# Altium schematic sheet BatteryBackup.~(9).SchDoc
size 431 x 279 mm; Date: Not shown in title block; ApprovedBy: Not shown in title block; CheckedBy: Not shown in title block; Author: Not shown in title block; CompanyName: Not shown in title block; Engineer: Not shown in title block; Organization: Not shown in title block; Address1: Not shown in title block; Address2: Not shown in title block; Address3: Not shown in title block; Address4: Not shown in title block; DocumentNumber: 1; Revision: Use project parameter SCH_Rev; SheetNumber: 1; SheetTotal: 2; PageSetup: Record=PageOptions¦CenterHorizontal=True¦CenterVertical=True¦PrintScale=1.00¦XCorrection=1.00¦YCorrection=1.00¦PrintKind=0¦BorderSize=5000000¦LeftOffset=0¦BottomOffset=0¦Orientation=2¦PaperLength=1000¦PaperWidth=1000¦Scale=100¦PaperSource=15¦PrintQuality=600¦MediaType=1¦DitherType=10¦PaperKind=Letter¦PrintScaleMode=1
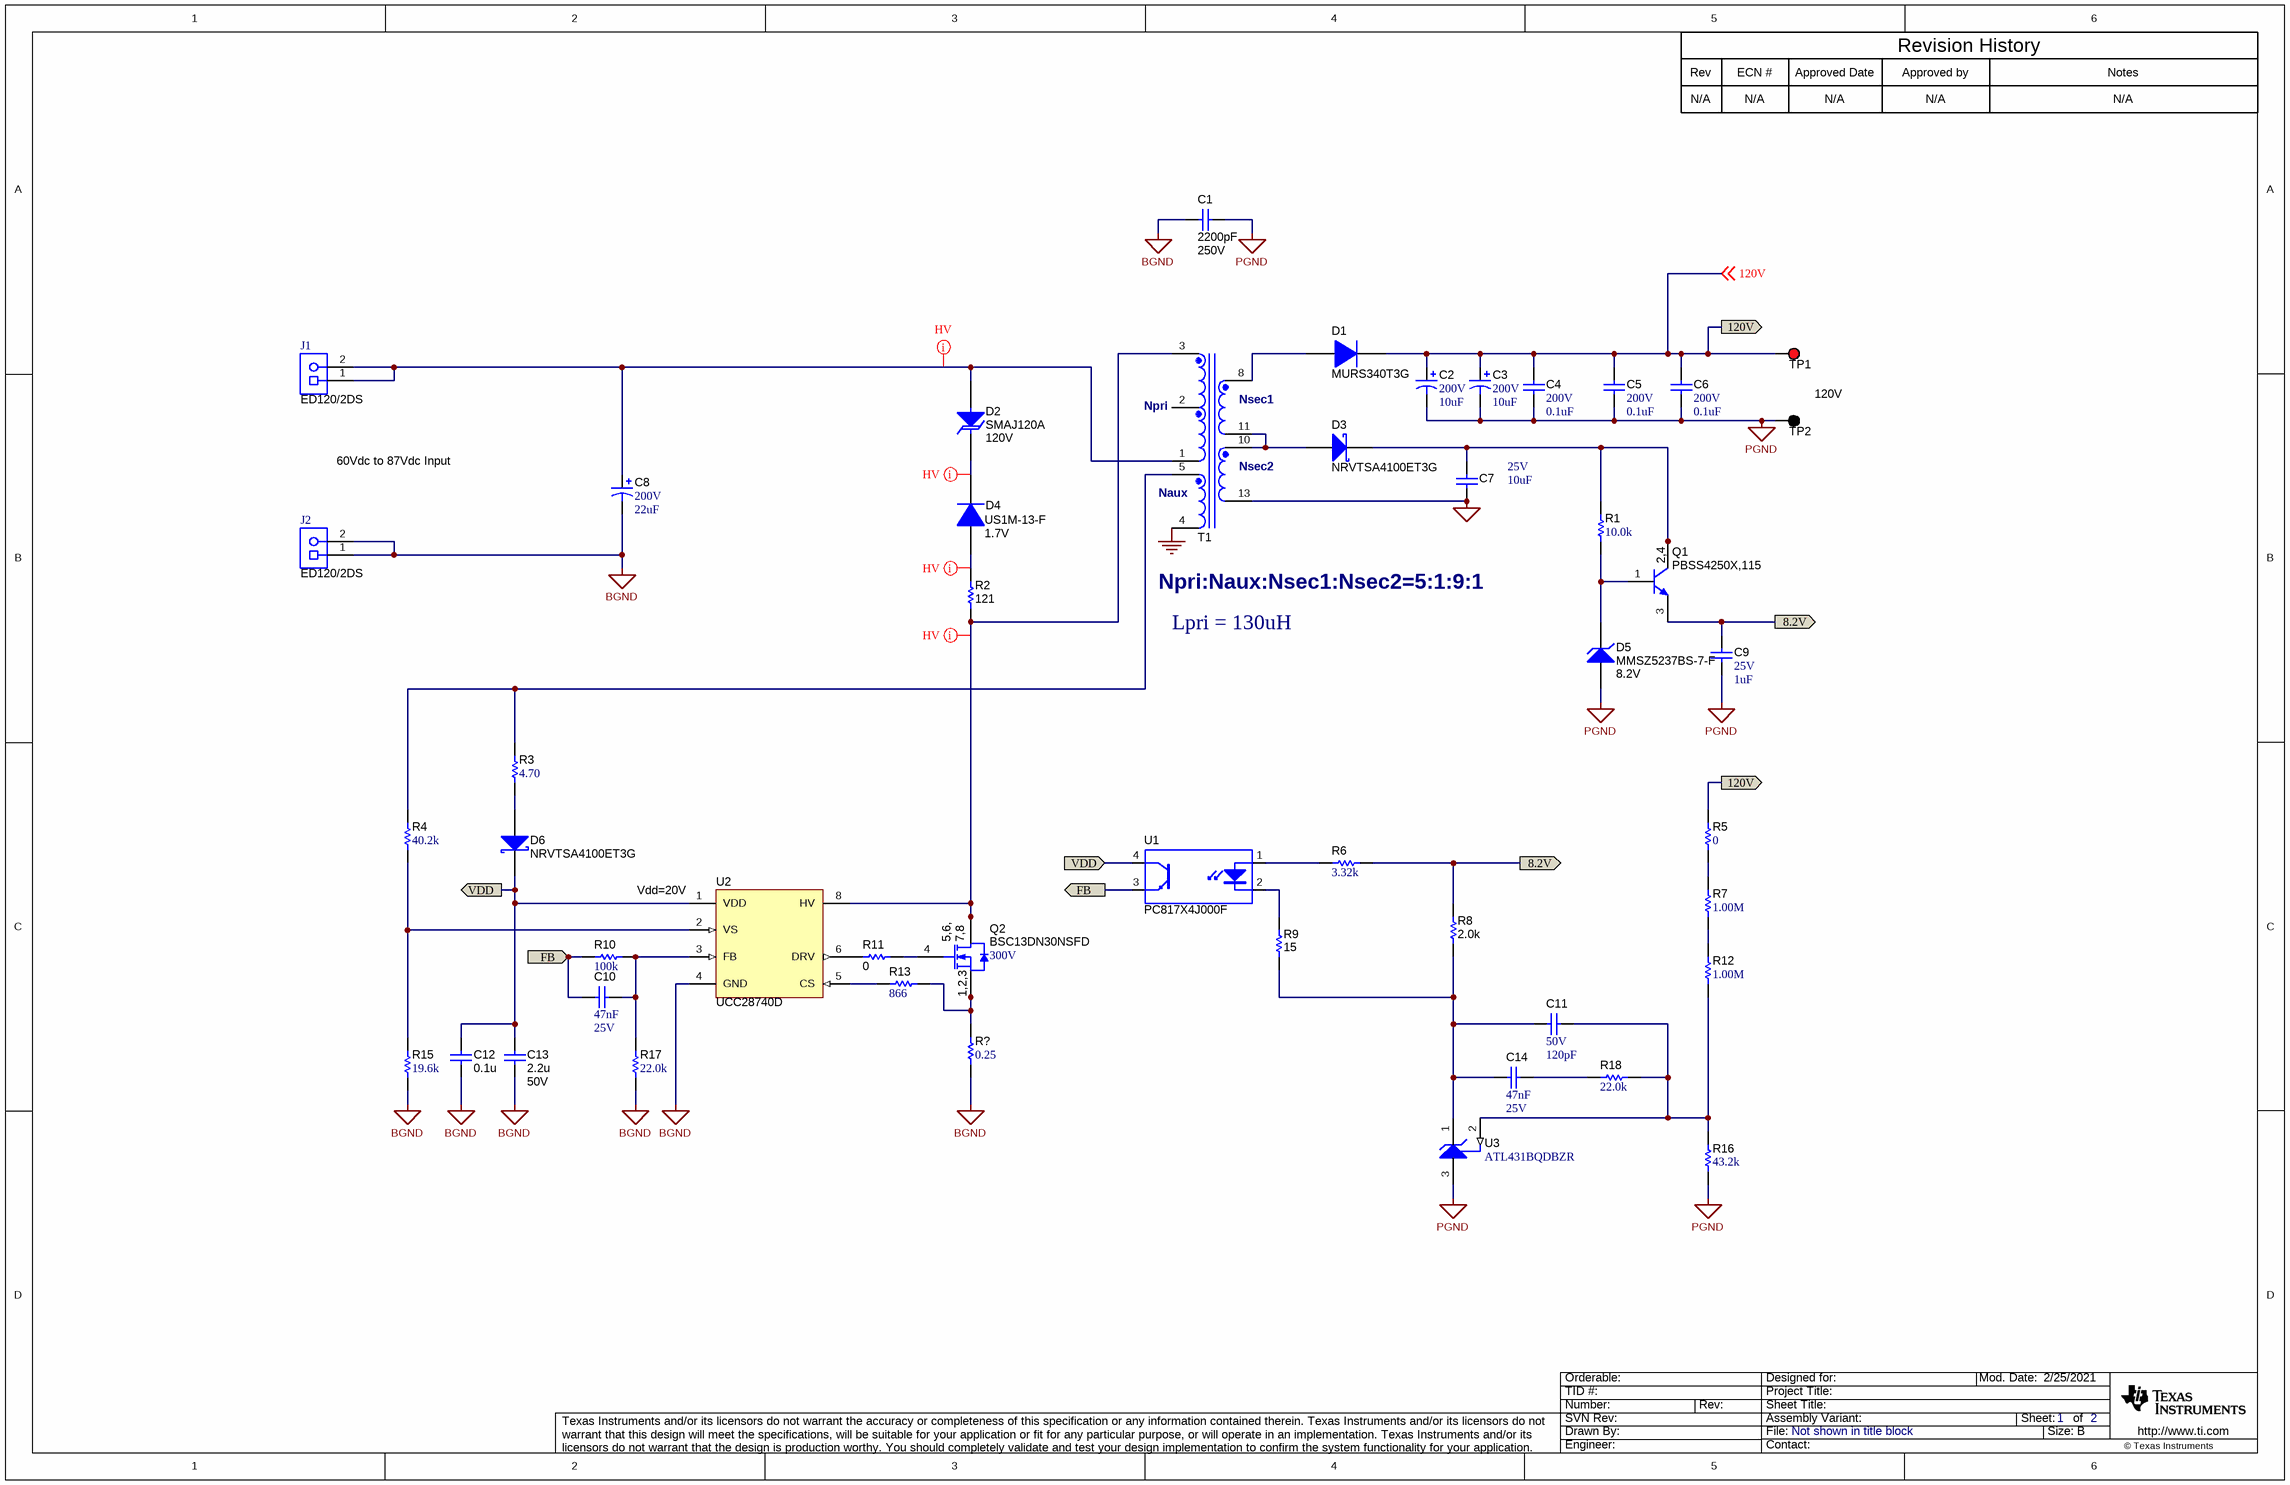
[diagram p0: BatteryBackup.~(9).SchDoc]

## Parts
C1  ValueDisplayed: 2200pF  Value2: 250V  [CAPRD750W60D1050H1450]  (hidden comment: CS11-E2GA222MYNS)
C2  VDC_V: 200V  ValueDisplayed: 10uF  [VK_800X1150]  (hidden comment: UVK2D100MPD)
C3  VDC_V: 200V  ValueDisplayed: 10uF  [VK_800X1150]  (hidden comment: UVK2D100MPD)
C4  VDC_V: 200V  ValueDisplayed: 0.1uF  [1206]  (hidden comment: C1206C104K2RACTU)
C5  VDC_V: 200V  ValueDisplayed: 0.1uF  [1206]  (hidden comment: C1206C104K2RACTU)
C6  VDC_V: 200V  ValueDisplayed: 0.1uF  [1206]  (hidden comment: C1206C104K2RACTU)
C7  VDC_V: 25V  ValueDisplayed: 10uF  [1206]  (hidden comment: TMK316BJ106KL-T)
C8  VDC_V: 200V  ValueDisplayed: 22uF  [UPW_1000x2000]  (hidden comment: UPW2D220MPD1TD)
C9  VDC_V: 25V  ValueDisplayed: 1uF  [0402]  (hidden comment: GRM155R61E105KA12D)
C10  Cap_F: 47nF  VDC_V: 25V  [0603]  (hidden comment: 06033C473JAT2A)
C11  VDC_V: 50V  ValueDisplayed: 120pF  [0603]  (hidden comment: VJ0603A121FXACW1BC)
C12  ValueDisplayed: 0.1u  [0603]  (hidden comment: 06035C104KAT2A)
C13  ValueDisplayed: 2.2u  Value2: 50V  [1206]  (hidden comment: GRM31CR61H225KA88L)
C14  Cap_F: 47nF  VDC_V: 25V  [0603]  (hidden comment: 06033C473JAT2A)
D1  MURS340T3G  [SMC]
D2  SMAJ120A  value 120V  [SMA]
D3  NRVTSA4100ET3G  [SMA]
D4  US1M-13-F  value 1.7V  [SMA]
D5  MMSZ5237BS-7-F  value 8.2V  [SOD-323]
D6  NRVTSA4100ET3G  [SMA]
J1  ED120/2DS  [On-Shore_ED120_2DS]
J2  ED120/2DS  [On-Shore_ED120_2DS]
Q1  PBSS4250X,115  [SOT-89-3]
Q2  BSC13DN30NSFD  value 300V  [PG-TDSON-8]
R1  ValueDisplayed: 10.0k  [0603]  (hidden comment: RCG060310K0FKEA)
R2  value 121  [1206]  (hidden comment: CRCW1206121RFKEA)
R3  ValueDisplayed: 4.70  [1206]  (hidden comment: RC1206FR-074R7L)
R4  ValueDisplayed: 40.2k  [0603]  (hidden comment: RC0603FR-0740K2L)
R5  ValueDisplayed: 0  [0603]  (hidden comment: RC0603JR-070RL)
R6  ValueDisplayed: 3.32k  [0603]  (hidden comment: RC0603FR-073K32L)
R7  ValueDisplayed: 1.00M  [1206]  (hidden comment: RC1206FR-071ML)
R8  value 2.0k  [1206]  (hidden comment: CRCW12062K00JNEA)
R9  value 15  [0603]  (hidden comment: CRCW060315R0JNEA)
R10  ValueDisplayed: 100k  [0603]  (hidden comment: RC0603FR-07100KL)
R11  value 0  [0603]  (hidden comment: CRCW06030000Z0EA)
R12  ValueDisplayed: 1.00M  [1206]  (hidden comment: RC1206FR-071ML)
R13  ValueDisplayed: 866  [0603]  (hidden comment: RC0603FR-07866RL)
R15  ValueDisplayed: 19.6k  [0603]  (hidden comment: RC0603FR-0719K6L)
R16  ValueDisplayed: 43.2k  [0603]  (hidden comment: RC0603FR-0743K2L)
R17  ValueDisplayed: 22.0k  [0603]  (hidden comment: RC0603FR-0722KL)
R18  ValueDisplayed: 22.0k  [0603]  (hidden comment: RC0603FR-0722KL)
R?  ValueDisplayed: 0.25  [1206]  (hidden comment: CSR1206FKR250)
T1  750314727  [WURTH_750314727]  (value not drawn)
TP1  5000  [Keystone5000]  (value not drawn)
TP2  5001  [Keystone5001]  (value not drawn)
U1  PC817X4J000F  [DIP762W60P254L460H350Q4B]
U2  UCC28740D  [D0007A_N]
U3  ATL431BQDBZR  [DBZ0003A_N]

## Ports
8.2V (out), 120V (out), FB (in), FB (out), VDD (in), VDD (out)

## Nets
BGND: C1.2 C8.2(-) C12.2 C13.2 J2.1 J2.2 R15.1 R17.1 R?.1 U2.4(GND)
GND: T1.4
GND2: C7.2 T1.13
PGND: C1.1 C2.2(-) C3.2(-) C4.2 C5.2 C6.2 C9.2 D5.2(A) R16.1 TP2.1 U3.3(ANODE)
8.2V: C9.1 Q1.3(E) R6.2 R8.2 ; port 8.2V
120V: C2.1(+) C3.1(+) C4.1 C5.1 C6.1 D1.1(K) R5.2 TP1.1 ; off-sheet 120V, port 120V
FB: C10.2 R10.1 U1.3(E) ; port FB
VDD: C12.1 C13.1 D6.1(K) U1.4(C) U2.1(VDD) ; port VDD
NetC7_1: C7.1 D3.1(K) Q1.2(C) Q1.4(C) R1.2
NetC8_1: C8.1(+) D2.2(A) J1.1 J1.2 T1.1
NetC10_1: C10.1 R10.2 R17.2 U2.3(FB)
NetC11_1: C11.1 R12.1 R16.2 R18.1 U3.2(REF)
NetC11_2: C11.2 C14.2 R8.1 R9.2 U3.1(CATHODE)
NetC14_1: C14.1 R18.2
NetD1_2: D1.2(A) T1.8
NetD2_1: D2.1(K) D4.1(K)
NetD3_2: D3.2(A) T1.10 T1.11
NetD4_2: D4.2(A) R2.2
NetD5_1: D5.1(K) Q1.1(B) R1.1
NetD6_2: D6.2(A) R3.1
NetQ2_1: Q2.1(S) Q2.2(S) Q2.3(S) R13.2 R?.2
NetQ2_4: Q2.4(G) R11.2
NetQ2_5: Q2.5(D) Q2.6(D) Q2.7(D) Q2.8(D) Q2.9(D) R2.1 T1.3 U2.8(HV)
NetR3_2: R3.2 R4.2 T1.5
NetR4_1: R4.1 R15.2 U2.2(VS)
NetR5_1: R5.1 R7.2
NetR6_1: R6.1 U1.1(A)
NetR7_1: R7.1 R12.2
NetR9_1: R9.1 U1.2(K)
NetR11_1: R11.1 U2.6(DRV)
NetR13_1: R13.1 U2.5(CS)

Not connected (* = marked no-connect by the designer): T1 2

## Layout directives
net class HV: NetC8_1, NetD2_1, NetD4_2, NetQ2_5

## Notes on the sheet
- Rev
- N/A
- ECN #
- Approved Date
- Approved by
- Revision History
- Notes
- (near T1) Npri
- (near T1) Nsec1
- 120V
- 60Vdc to 87Vdc Input
- (near T1) Naux
- (near T1) Nsec2
- (near T1) Npri:Naux:Nsec1:Nsec2=5:1:9:1
- Lpri = 130uH
- (near U2) Vdd=20V

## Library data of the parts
C1 = CS11-E2GA222MYNS: CAP, CERM, 2200pF, 250V, +/-20%, E, Radial Disc D10.5x7mm; Manufacturer: TDK; Polarized: N; CompType: Capacitor; U/M: EA; Cap_F: 0.0000000022; Tolerance_%: 20; Value1: Unknown; VDC_V: 250; TaMin_C: -25; TaMax_C: 105; Cap_Case: Disc, 10.5x7mm
C2 C3 = CMP-0064891-1: CAP, AL, 10 uF, 200 V, +/- 20%, TH; Manufacturer: Nichicon; TaMin_C: -40°C; Polarized: Y; SizeAreaWB_mm2: 100; Value1: Unknown; U/M: EA; Value: 10uF; TaMax_C: 85°C; SizeZ_mm: 13; SizeX_mm: 8; Cap_Case: 8x11.5mm; SizeArea_mm2: 64; CompType: Capacitor; AEC Qualified: N; Cap_F: 10µF; IRMS_A: 80mA; AEC Category: Q200
C4-C6 = CMP-0008585-2: CAP, CERM, 0.1 uF, 200 V, +/- 10%, X7R, 1206; Manufacturer: Kemet; TaMin_C: -55°C; Polarized: N; SizeAreaWB_mm2: 10.92; Value1: Unknown; U/M: EA; Value: 0.1uF; TaMax_C: 125°C; SizeZ_mm: 1.35; SizeX_mm: 3.2; SizeY_mm: 1.6; SizeArea_mm2: 5.12; Cap_F: 100nF; AEC Category: Q200
C7 = CMP-0009025-2: CAP, CERM, 10 uF, 25 V, +/- 10%, X5R, 1206; Manufacturer: Taiyo Yuden; TaMin_C: -55°C; Polarized: N; SizeAreaWB_mm2: 10.92; Value1: Unknown; U/M: EA; Value: 10uF; TaMax_C: 85°C; SizeZ_mm: 1.35; SizeX_mm: 3.2; SizeY_mm: 1.6; SizeArea_mm2: 5.12; Cap_F: 10µF; AEC Category: Q200
C8 = CMP-0064890-1: CAP, AL, 22 uF, 200 V, +/- 20%, TH; Manufacturer: Nichicon; TaMin_C: -40°C; Polarized: Y; SizeAreaWB_mm2: 144; Value1: Unknown; U/M: EA; Value: 22uF; TaMax_C: 105°C; SizeZ_mm: 22; SizeX_mm: 10; Cap_Case: 10x20mm; SizeArea_mm2: 100; CompType: Capacitor; AEC Qualified: N; Cap_F: 22µF; IRMS_A: 1.4dA; AEC Category: Q200
C9 = CMP-0006608-2: CAP, CERM, 1 uF, 25 V, +/- 10%, X5R, 0402; Manufacturer: MuRata; TaMin_C: -55°C; Polarized: N; SizeAreaWB_mm2: 3; Value1: Unknown; U/M: EA; Value: 1uF; TaMax_C: 85°C; SizeZ_mm: 0.6; SizeX_mm: 1; SizeY_mm: 0.5; Cap_F: 1µF; AEC Category: Q200
C10 C14 = CMP-0006757-5: CAP, CERM, 0.047 uF, 25 V, +/- 5%, X7R, 0603; Manufacturer: AVX; TaMin_C: -55°C; ESR_ohm: 0.052; Polarized: N; SizeAreaWB_mm2: 4.68; Value1: 0.052 ohm; U/M: EA; TaMax_C: 125°C; SizeZ_mm: 1; SizeX_mm: 1.6; SizeY_mm: 0.8; SizeArea_mm2: 1.28; AEC Category: Q200
C11 = CMP-0007510-4: CAP, CERM, 120 pF, 50 V, +/- 1%, C0G/NP0, 0603; Manufacturer: Vishay-Sprague; TaMin_C: -55°C; Polarized: N; SizeAreaWB_mm2: 4.68; Value1: Unknown; U/M: EA; Value: 120pF; TaMax_C: 125°C; SizeZ_mm: 1; SizeX_mm: 1.6; SizeY_mm: 0.8; SizeArea_mm2: 1.28; AEC Category: Q200
C12 = 06035C104KAT2A: CAP, CERM, 0.1uF, 50V, +/-10%, X7R, 0603; Manufacturer: AVX; Polarized: N; CompType: Capacitor; U/M: EA; Cap_F: 0.0000001; Tolerance_%: 10; Value1: Unknown; VDC_V: 50; TaMin_C: -55; TaMax_C: 125
C13 = GRM31CR61H225KA88L: CAP, CERM, 2.2uF, 50V, +/-10%, X5R, 1206; Manufacturer: MuRata; Polarized: N; CompType: Capacitor; U/M: EA; Cap_F: 0.0000022; Tolerance_%: 10; Value1: Unknown; VDC_V: 50; TaMin_C: -55; TaMax_C: 85
D1 = CMP-0076962-2: Diode, Ultrafast, 400 V, 3 A, SMC; Manufacturer: ON Semiconductor; AEC Category: Q101; Io_A: 3A; RJC_CperW: 11.0; SizeArea_mm2: 50.5686; SizeX_mm: 8.13; SizeZ_mm: 2.6; SizeAreaWB_mm2: 83.2686; TJmax_C: 175°C; Green_REACh: Incomplete; Value2: 1.25V; Vr_V: 400V; Green_Lifecycle: Not Set; SizeY_mm: 6.22; Value: 400V
D2 = SMAJ120A: Diode, TVS, Uni, 120V, 400W, SMA; Manufacturer: Littelfuse; U/M: EA; Power_W: 400; Vr_V: 120
D3 D6 = CMP-0081057-2: Diode, Schottky, 100 V, 4 A, AEC-Q101, SMA; Manufacturer: ON Semiconductor; SizeZ_mm: 2.87; SizeY_mm: 2.92; SizeAreaWB_mm2: 37.3428; Io_A: 4A; AEC Category: Q101; SizeX_mm: 5.59; Value: 100V; SizeArea_mm2: 16.3228; Value2: 0.68V; TJmax_C: 175°C; AEC Qualified: Y; Vf_V: 680mV
D4 = US1M-13-F: Diode, Ultrafast, 1000V, 1A, SMA; Manufacturer: Diodes Inc.; U/M: EA; Vf_V: 1.7; Io_A: 1; Vr_V: 1000; TJmax_C: 150; RJC_CperW: 30
D5 = CMP-0005860-3: Diode, Zener, 8.2 V, 200 mW, SOD-323; Manufacturer: Diodes Inc.; Value1: 0.2W; Power_W: 200mW; SizeX_mm: 2.7; SizeY_mm: 1.35; SizeAreaWB_mm2: 8.695; RJA_CperW: 350; SizeArea_mm2: 3.645; AEC Category: Q101; SizeZ_mm: 1
J1 J2 = CMP-0074910-1: Terminal Block, 5.08 mm, 2x1, Brass, TH; Manufacturer: On-Shore Technology; Cert_VDE: Y; CNHeader: False; Current_A: 15A; Green_Lifecycle: Not Set; Shrouded: N; Gender: Female; Green_REACh: Incomplete; Voltage_V: 300V; Row_Count: 1; Pitch_mm: 5.08; CT: True
Q1 = CMP-0000491-2: Transistor, NPN, 50 V, 2 A, SOT-89; Manufacturer: NXP Semiconductor; TaMax_C: 150°C; Value1: 2 A; Vcesat1_V: 2.5dV; SizeX_mm: 4.1; SizeY_mm: 4.5; TaMin_C: -65°C; IcRated_A: 2A; CompType: BJT; SizeZ_mm: 1.5; AEC Qualified: N; Value: 50 V; SizeArea_mm2: 18.45; NPN: 1; Vceo_V: 50V; PNP: 0; AEC Category: Q101; SizeAreaWB_mm2: 28.05; U/M: EA
Q2 = CMP-0000907-1: MOSFET, N-CH, 300 V, 16 A, PG-TDSON-8; Alternate Manufacturer: None; Manufacturer: Infineon Technologies; SizeZ_mm: 1.12; ChType: N; SizeX_mm: 5.99; SizeY_mm: 4.9; Vgs_V: 20V; SizeArea_mm2: 29.351; IdsMax_A: 16A; SizeAreaWB_mm2: 55.131; U/M: EA; QgTyp_nC: 23
R1 = CMP-0023337-3: RES, 10.0 k, 1%, 0.1 W, 0603; Manufacturer: Vishay Draloric; Power_W: 100mW; TempCo: 100 ppm/C; Value_Code: 10k0; U/M: EA; Value: 10.0k; EIA_Code: E96; Res_ohm: 10k; SizeX_mm: 1.6; SizeY_mm: 0.8; SizeZ_mm: 1; Value2: 0.1W; SizeArea_mm2: 1.28; AEC Qualified: N; VDC_V: 75V; AEC Category: Q200
R2 = CRCW1206121RFKEA: RES, 121 ohm, 1%, 0.25W, 1206; Manufacturer: Vishay-Dale; CompType: Resistor; Value_Code: 121R; Tolerance_%: 1; Power_W: 0.25; VDC_V: 200; TempCo: 100 ppm/C; EIA_Code: E96; U/M: EA
R3 = CMP-0018350-2: RES, 4.70, 1%, 0.25 W, 1206; Manufacturer: Yageo America; Power_W: 250mW; TempCo: 200 ppm/C; Value_Code: 4R70; U/M: EA; Value: 4.70; Res_ohm: 4.7; SizeX_mm: 3.2; SizeY_mm: 1.6; SizeZ_mm: 1.35; Value2: 0.25W; SizeArea_mm2: 5.12; VDC_V: 200V; AEC Category: Q200
R4 = CMP-0023098-5: RES, 40.2 k, 1%, 0.1 W, 0603; Manufacturer: Yageo; Power_W: 100mW; TempCo: 100 ppm/C; Value_Code: 40k2; Value: 40.2k; EIA_Code: E96; SizeX_mm: 1.6; SizeY_mm: 0.8; SizeZ_mm: 1; Value2: 0.1W; SizeArea_mm2: 1.28; AEC Qualified: N; VDC_V: 75V; AEC Category: Q200; SizeAreaWB_mm2: 4.68
R5 = CMP-0025885-5: RES, 0, 5%, 0.1 W, 0603; Manufacturer: Yageo; Power_W: 100mW; TempCo: 200 ppm/C; Value_Code: 0000; Value: 0; EIA_Code: E24; SizeX_mm: 1.6; SizeZ_mm: 1; Value2: 0.1W; SizeArea_mm2: 1.28; AEC Qualified: N; VDC_V: 75V; AEC Category: Q200; SizeY_mm: 0.8; SizeAreaWB_mm2: 4.68
R6 = CMP-0023080-5: RES, 3.32 k, 1%, 0.1 W, 0603; Manufacturer: Yageo; Power_W: 100mW; TempCo: 100 ppm/C; Value_Code: 3k32; Value: 3.32k; EIA_Code: E96; SizeX_mm: 1.6; SizeY_mm: 0.8; SizeZ_mm: 1; Value2: 0.1W; SizeArea_mm2: 1.28; AEC Qualified: N; VDC_V: 75V; AEC Category: Q200; SizeAreaWB_mm2: 4.68
R7 R12 = CMP-0018027-2: RES, 1.00 M, 1%, 0.25 W, 1206; Manufacturer: Yageo America; Power_W: 250mW; TempCo: 100 ppm/C; Value_Code: 1M00; U/M: EA; Value: 1.00Meg; EIA_Code: E96; Res_ohm: 1M; SizeX_mm: 3.2; SizeY_mm: 1.6; SizeZ_mm: 1.35; Value2: 0.25W; SizeArea_mm2: 5.12; VDC_V: 200V; AEC Category: Q200
R8 = CRCW12062K00JNEA: RES, 2.0k ohm, 5%, 0.25W, 1206; Manufacturer: Vishay-Dale; CompType: Resistor; Res_ohm: 2000; Value_Code: 2k00; Tolerance_%: 5; Power_W: 0.25; VDC_V: 200; TempCo: 200 ppm/C; EIA_Code: E24; U/M: EA
R9 = CRCW060315R0JNEA: RES, 15 ohm, 5%, 0.1W, 0603; Manufacturer: Vishay-Dale; CompType: Resistor; Value_Code: 15R0; Tolerance_%: 5; Power_W: 0.1; VDC_V: 75; TempCo: 200 ppm/C; EIA_Code: E24; U/M: EA
R10 = CMP-0022735-5: RES, 100 k, 1%, 0.1 W, 0603; Manufacturer: Yageo; Power_W: 100mW; TempCo: 100 ppm/C; Value: 100k; EIA_Code: E96; SizeX_mm: 1.6; SizeY_mm: 0.8; SizeZ_mm: 1; Value2: 0.1W; SizeArea_mm2: 1.28; AEC Qualified: N; VDC_V: 75V; AEC Category: Q200; SizeAreaWB_mm2: 4.68
R11 = CRCW06030000Z0EA: RES, 0 ohm, 5%, 0.1W, 0603; Manufacturer: Vishay-Dale; CompType: Resistor; Value_Code: 0000; Tolerance_%: 5; Power_W: 0.1; VDC_V: 75; TempCo: 200 ppm/C; EIA_Code: E24; U/M: EA
R13 = CMP-0023300-5: RES, 866, 1%, 0.1 W, 0603; Manufacturer: Yageo; Power_W: 100mW; TempCo: 100 ppm/C; Value_Code: 866R; Value: 866; EIA_Code: E96; SizeX_mm: 1.6; SizeY_mm: 0.8; SizeZ_mm: 1; Value2: 0.1W; SizeArea_mm2: 1.28; AEC Qualified: N; VDC_V: 75V; AEC Category: Q200; SizeAreaWB_mm2: 4.68
R15 = CMP-0022861-5: RES, 19.6 k, 1%, 0.1 W, 0603; Manufacturer: Yageo; Power_W: 100mW; TempCo: 100 ppm/C; Value_Code: 19k6; Value: 19.6k; EIA_Code: E96; SizeX_mm: 1.6; SizeY_mm: 0.8; SizeZ_mm: 1; Value2: 0.1W; SizeArea_mm2: 1.28; AEC Qualified: N; VDC_V: 75V; AEC Category: Q200; SizeAreaWB_mm2: 4.68
R16 = CMP-0023112-5: RES, 43.2 k, 1%, 0.1 W, 0603; Manufacturer: Yageo; Power_W: 100mW; TempCo: 100 ppm/C; Value_Code: 43k2; Value: 43.2k; EIA_Code: E96; SizeX_mm: 1.6; SizeY_mm: 0.8; SizeZ_mm: 1; Value2: 0.1W; SizeArea_mm2: 1.28; AEC Qualified: N; VDC_V: 75V; AEC Category: Q200; SizeAreaWB_mm2: 4.68
R17 R18 = CMP-0022925-5: RES, 22.0 k, 1%, 0.1 W, 0603; Manufacturer: Yageo; Power_W: 100mW; TempCo: 100 ppm/C; Value_Code: 22k0; Value: 22.0k; Res_ohm: 22k; SizeX_mm: 1.6; SizeY_mm: 0.8; SizeZ_mm: 1; Value2: 0.1W; SizeArea_mm2: 1.28; AEC Qualified: N; VDC_V: 75V; AEC Category: Q200; SizeAreaWB_mm2: 4.68
R? = CMP-0017267-2: RES, 0.25, 1%, 0.5 W, 1206; Manufacturer: Stackpole Electronics Inc; Power_W: 500mW; TempCo: 100 ppm/C; Value_Code: R250; U/M: EA; Value: 0.25; Res_ohm: 2.5d; SizeX_mm: 3.2; SizeY_mm: 1.6; SizeZ_mm: 1.35; Value2: 0.5W; SizeArea_mm2: 5.12; AEC Category: Q200
T1 = 750314727: Transformer, 80uH, TH; Manufacturer: Wurth Elektronik eiSos; SymbolCreator: x0208325; DCR_Ohm: 0.221; Value: 250uH; LeakageL: TBD; U/M: EA
TP1 = 5000: Test Point, TH, Miniature, Red; Manufacturer: Keystone; CompType: Test Point Loop; U/M: EA
TP2 = 5001: Test Point, TH, Miniature, Black; Manufacturer: Keystone; CompType: Test Point Loop; U/M: EA
U1 = LTV-817: Opto-Isolator, 1 Channel, TH; CompType: OPTOCOUPLER; U/M: EA
U2 = UCC28740D: Constant-Voltage, Constant-Current Flyback Controller Using Opto-Coupler Feedback, D0007A; Alternate Manufacturer: None; Manufacturer: Texas Instruments; SymbolCreator: a0412235; CompType: IC; U/M: EA
U3 = CMP-0066200-1: 2.5V Low Iq Adjustable Precision Shunt Regulator, DBZ0003A (SOT-23-3); Alternate PartNumber: ATL431BQDBZT; Alternate Manufacturer: Texas Instruments; Green_Lifecycle: Active; SizeAreaWB_mm2: 14.0; Green_REACh: Passed; U/M: EA; SizeZ_mm: 1.12; SizeX_mm: 2.5; SizeY_mm: 3.0; SizeArea_mm2: 7.5; CompType: IC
